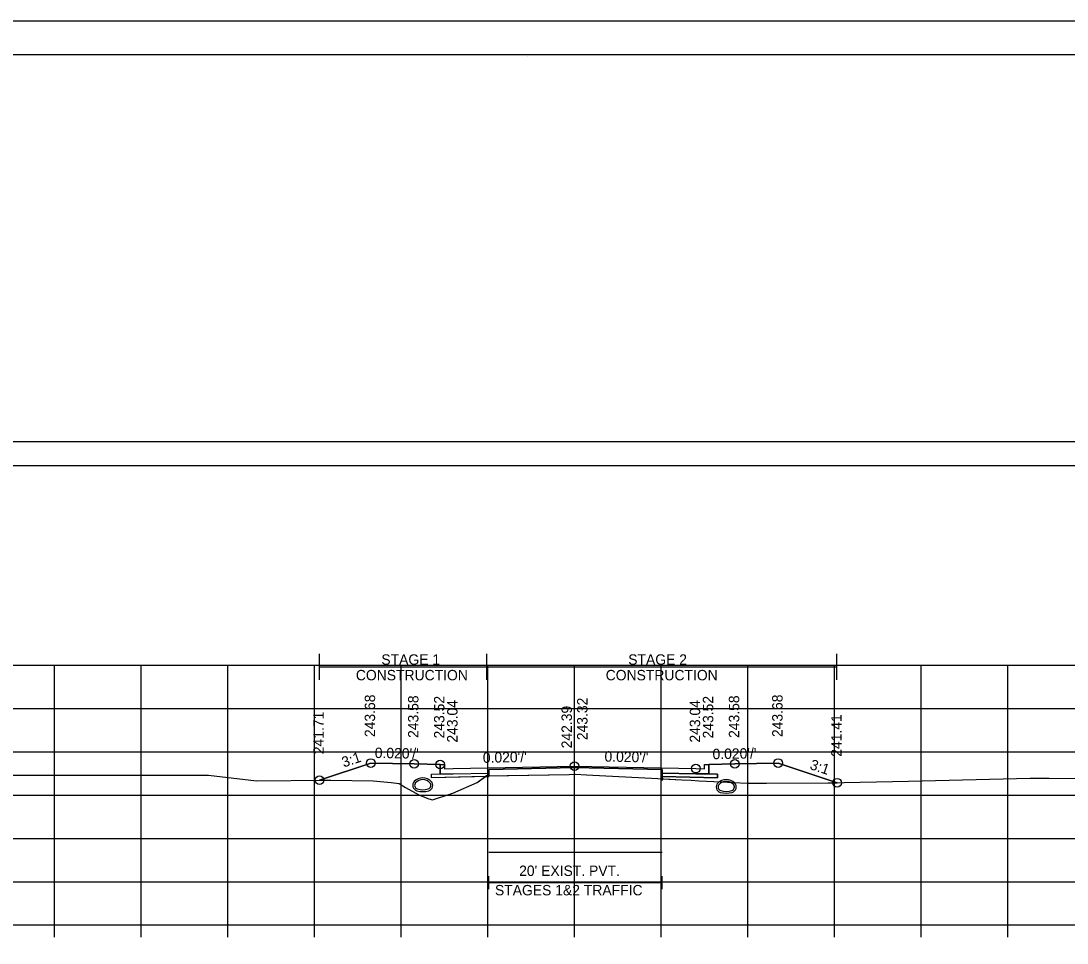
# Model space of a CAD drawing. Extents: x 1369627 to 1374022, y 380035 to 398173.
# Drawn here: x 1372034.6 to 1372155.4, y 383132.4 to 383238.8 of the extents above; entities that cross this region are included whole.
import ezdxf

# ---------------------------------------------------------------- set-up
doc = ezdxf.new("R2010")
doc.units = 0
for name, color, linetype in [('Default', 7, 'Continuous'), ('R_Alt Surface', 7, 'Continuous'), ('R_Axis', 7, 'Continuous'), ('R_Axis Annot', 7, 'Continuous'), ('R_Border', 7, 'Continuous'), ('R_Exist Surface', 7, 'Continuous'), ('R_Fin Surface', 7, 'Continuous'), ('R_Grid', 7, 'Continuous'), ('R_MOT', 7, 'Continuous'), ('R_No Plot', 7, 'Continuous'), ('R_Water', 7, 'Continuous'), ('R_Xsect Elev', 7, 'Continuous'), ('R_Xsect Slope', 7, 'Continuous'), ('T_Vehicle Path Rt', 7, 'Continuous')]:
    doc.layers.add(name, color=color, linetype=linetype)

msp = doc.modelspace()

# ---------------------------------------------------------------- linework, layer by layer
at = {"layer": 'Default'}
for p, q in [((1372088.64, 383138.64), (1372088.64, 383140.14)), ((1372088.64, 383139.39), (1372108.64, 383139.39)), ((1372108.64, 383138.64), (1372108.64, 383140.14))]:
    msp.add_line(p, q, dxfattribs=at)
msp.add_lwpolyline([(1371948.53, 383187.54), (1372248.53, 383187.54), (1372248.53, 383190.24), (1371948.53, 383190.24)], close=True, dxfattribs=at)
at = {"layer": 'R_Alt Surface'}
msp.add_lwpolyline([(1372083.03, 383153.02), (1372083.03, 383151.92), (1372084.53, 383151.95), (1372088.64, 383152.03), (1372088.64, 383152.45), (1372098.53, 383152.65), (1372108.64, 383152.44), (1372108.64, 383152.03), (1372112.53, 383151.95), (1372114.03, 383151.92), (1372114.03, 383153.02)], dxfattribs=at)
for points in [[(1372082.03, 383151.9), (1372083.03, 383151.92), (1372084.53, 383151.95), (1372088.64, 383152.03), (1372088.64, 383151.61), (1372082.03, 383151.48)], [(1372115.03, 383151.9), (1372114.03, 383151.92), (1372112.53, 383151.95), (1372108.64, 383152.03), (1372108.64, 383151.61), (1372115.03, 383151.48)]]:
    msp.add_lwpolyline(points, close=True, dxfattribs=at)
at = {"layer": 'R_Axis'}
for p, q in [((1371948.53, 383134.49), (1372248.53, 383134.49)), ((1372038.53, 383133.09), (1372038.53, 383134.49)), ((1372048.53, 383133.09), (1372048.53, 383134.49)), ((1372058.53, 383133.09), (1372058.53, 383134.49)), ((1372068.53, 383133.09), (1372068.53, 383134.49)), ((1372078.53, 383133.09), (1372078.53, 383134.49)), ((1372088.53, 383133.09), (1372088.53, 383134.49)), ((1372098.53, 383133.09), (1372098.53, 383134.49)), ((1372108.53, 383133.09), (1372108.53, 383134.49)), ((1372118.53, 383133.09), (1372118.53, 383134.49)), ((1372128.53, 383133.09), (1372128.53, 383134.49)), ((1372138.53, 383133.09), (1372138.53, 383134.49)), ((1372148.53, 383133.09), (1372148.53, 383134.49))]:
    msp.add_line(p, q, dxfattribs=at)
at = {"layer": 'R_Border'}
for p, q in [((1371940.53, 383234.95), (1372256.71, 383234.95)), ((1372093.05, 383234.69), (1372093.05, 383234.69)), ((1372093.05, 383234.69), (1372093.05, 383234.69))]:
    msp.add_line(p, q, dxfattribs=at)
at = {"layer": 'R_Exist Surface'}
msp.add_lwpolyline([(1372015.27, 383151.77), (1372044.13, 383151.79), (1372055.21, 383151.8), (1372056.3, 383151.77), (1372061.83, 383151.14), (1372069.81, 383151.21), (1372070.09, 383151.19), (1372070.42, 383151.19), (1372075.29, 383151.13), (1372077.37, 383150.93), (1372078.3, 383150.83), (1372079.04, 383150.37), (1372080.64, 383149.46), (1372081.71, 383149.05), (1372082.14, 383148.92), (1372084.24, 383149.61), (1372084.35, 383149.65), (1372084.5, 383149.72), (1372087.28, 383150.95), (1372088.26, 383151.63), (1372088.37, 383151.72), (1372097.93, 383151.87), (1372098.64, 383151.88), (1372099.9, 383151.82), (1372108.16, 383151.4), (1372110.92, 383151.24), (1372111.98, 383151.19), (1372112.89, 383151.14), (1372115.49, 383151.01), (1372116.88, 383150.94), (1372118.46, 383150.85), (1372120.7, 383150.86), (1372127.81, 383150.88), (1372137.06, 383151.09), (1372151.12, 383151.43), (1372153.3, 383151.43), (1372172.84, 383151.22)], dxfattribs=at)
at = {"layer": 'R_Fin Surface'}
msp.add_lwpolyline([(1372069.1, 383151.2), (1372075.02, 383153.18), (1372080.02, 383153.08), (1372083.02, 383153.02), (1372083.52, 383153.02), (1372083.53, 383152.52), (1372084.53, 383152.54), (1372086.53, 383152.58), (1372098.53, 383152.82), (1372110.53, 383152.58), (1372112.53, 383152.54), (1372113.53, 383152.52), (1372113.54, 383153.02), (1372114.04, 383153.02), (1372117.04, 383153.08), (1372122.04, 383153.18), (1372128.85, 383150.91)], dxfattribs=at)
at = {"layer": 'R_Grid'}
for p, q in [((1371948.53, 383164.49), (1372248.53, 383164.49)), ((1372038.53, 383134.49), (1372038.53, 383164.49)), ((1372048.53, 383134.49), (1372048.53, 383164.49)), ((1372058.53, 383134.49), (1372058.53, 383164.49)), ((1372068.53, 383134.49), (1372068.53, 383164.49)), ((1372078.53, 383134.49), (1372078.53, 383164.49)), ((1372088.53, 383134.49), (1372088.53, 383164.49)), ((1372098.53, 383134.49), (1372098.53, 383164.49)), ((1372108.53, 383134.49), (1372108.53, 383164.49)), ((1372118.53, 383134.49), (1372118.53, 383164.49)), ((1372128.53, 383134.49), (1372128.53, 383164.49)), ((1372138.53, 383134.49), (1372138.53, 383164.49)), ((1372148.53, 383134.49), (1372148.53, 383164.49)), ((1371948.53, 383159.49), (1372248.53, 383159.49)), ((1371948.53, 383154.49), (1372248.53, 383154.49)), ((1371948.53, 383149.49), (1372248.53, 383149.49)), ((1371948.53, 383144.49), (1372248.53, 383144.49)), ((1371948.53, 383139.49), (1372248.53, 383139.49)), ((1371948.53, 383134.49), (1372248.53, 383134.49))]:
    msp.add_line(p, q, dxfattribs=at)
at = {"layer": 'R_MOT'}
for p, q in [((1372069.1, 383162.77), (1372069.1, 383165.77)), ((1372088.4, 383162.77), (1372088.4, 383165.77)), ((1372128.79, 383162.77), (1372128.79, 383165.77)), ((1372069.1, 383164.27), (1372128.79, 383164.27))]:
    msp.add_line(p, q, dxfattribs=at)
at = {"layer": 'R_No Plot'}
msp.add_line((1371928.13, 383238.84), (1372261.46, 383238.84), dxfattribs=at)
for points in [[(1371928.12, 383238.84), (1372261.46, 383238.84), (1372261.46, 383025.5), (1371928.12, 383025.5)], [(1372174.45, 383234.95), (1372194.07, 383234.95), (1372194.07, 383225.07), (1372210.18, 383225.07), (1372233.38, 383225.07), (1372233.38, 383192.4), (1372256.59, 383192.4), (1372256.71, 383029.49), (1371940.53, 383029.49), (1371940.53, 383234.95)]]:
    msp.add_lwpolyline(points, close=True, dxfattribs=at)
msp.add_lwpolyline([(1372088.64, 383142.88), (1372108.64, 383142.88)], dxfattribs=at)
for centre in [(1372075.02, 383153.18), (1372080.02, 383153.08), (1372083.02, 383153.02), (1372098.53, 383152.82), (1372112.53, 383152.54), (1372117.04, 383153.08), (1372122.04, 383153.18), (1372069.1, 383151.2), (1372128.85, 383150.91)]:
    msp.add_circle(centre, 0.5, dxfattribs=at)
at = {"layer": 'R_Water'}
for centre, radius, start, end in [((1372081.02, 383150.12), 1.35, 43.6485, 136.3515), ((1372080.51, 383150.61), 0.646, 136.3515, 253.9529), ((1372080.51, 383150.61), 0.438, 136.3515, 253.9529), ((1372081.02, 383150.12), 1.15, 43.6485, 136.3515), ((1372081.02, 383152.39), 2.29, 253.9529, 286.0471), ((1372081.53, 383150.61), 0.438, 286.0471, 43.6485), ((1372081.53, 383150.61), 0.646, 286.0471, 43.6485), ((1372115.53, 383150.42), 0.646, 136.3515, 253.9529), ((1372116.04, 383149.93), 1.35, 43.6485, 136.3515), ((1372115.53, 383150.42), 0.438, 136.3515, 253.9529), ((1372116.04, 383149.93), 1.15, 43.6485, 136.3515), ((1372116.55, 383150.42), 0.438, 286.0471, 43.6485), ((1372116.55, 383150.42), 0.646, 286.0471, 43.6485), ((1372081.02, 383152.39), 2.5, 253.9529, 286.0471), ((1372116.04, 383152.2), 2.5, 253.9529, 286.0471), ((1372116.04, 383152.2), 2.29, 253.9529, 286.0471)]:
    msp.add_arc(centre, radius, start, end, dxfattribs=at)
at = {"layer": 'R_Xsect Elev'}
msp.add_line((1372098.53, 383151.88), (1372098.53, 383161.88), dxfattribs=at)
at = {"layer": 'T_Vehicle Path Rt'}
for p, q in [((1372083.03, 383151.92), (1372083.03, 383153.02)), ((1372114.04, 383153.02), (1372114.03, 383151.92)), ((1372088.23, 383151.61), (1372082.03, 383151.48)), ((1372088.23, 383151.61), (1372088.64, 383151.61)), ((1372088.64, 383152.03), (1372088.64, 383151.72)), ((1372088.64, 383151.61), (1372088.64, 383151.72)), ((1372108.64, 383151.61), (1372108.64, 383152.03)), ((1372108.64, 383151.61), (1372108.64, 383151.16)), ((1372108.64, 383151.37), (1372108.64, 383151.61)), ((1372108.64, 383151.61), (1372108.64, 383151.37)), ((1372108.64, 383151.37), (1372110.92, 383151.24))]:
    msp.add_line(p, q, dxfattribs=at)
for points in [[(1372083.03, 383153.02), (1372083.02, 383153.02), (1372080.02, 383153.08), (1372075.02, 383153.18), (1372069.1, 383151.2)], [(1372108.64, 383152.03), (1372108.64, 383152.44), (1372098.53, 383152.65), (1372088.64, 383152.45), (1372088.64, 383152.03)], [(1372128.85, 383150.91), (1372122.04, 383153.18), (1372117.04, 383153.08), (1372114.04, 383153.02)], [(1372069.1, 383151.2), (1372069.81, 383151.21), (1372070.09, 383151.19), (1372070.42, 383151.19), (1372075.29, 383151.13), (1372077.37, 383150.93), (1372078.3, 383150.83), (1372079.04, 383150.37), (1372080.64, 383149.46), (1372081.71, 383149.05), (1372082.14, 383148.92), (1372084.24, 383149.61), (1372084.35, 383149.65), (1372084.5, 383149.72), (1372087.28, 383150.95), (1372088.23, 383151.61)], [(1372082.03, 383151.48), (1372082.03, 383151.9), (1372083.03, 383151.92)], [(1372088.64, 383151.72), (1372088.37, 383151.72), (1372088.26, 383151.63), (1372088.23, 383151.61)], [(1372088.64, 383151.72), (1372097.93, 383151.87), (1372098.64, 383151.88), (1372099.9, 383151.82), (1372108.16, 383151.4), (1372108.64, 383151.37)], [(1372114.03, 383151.92), (1372115.03, 383151.9), (1372115.03, 383151.48), (1372108.64, 383151.61)], [(1372110.92, 383151.24), (1372111.98, 383151.19), (1372112.89, 383151.14), (1372115.49, 383151.01), (1372116.88, 383150.94), (1372118.46, 383150.85), (1372120.7, 383150.86), (1372127.81, 383150.88), (1372128.85, 383150.91)]]:
    msp.add_lwpolyline(points, dxfattribs=at)

# ---------------------------------------------------------------- texts
at = {"layer": 'R_Axis Annot'}
for s, p in [("20' EXIST. PVT.", (1372092.14, 383140.15)), ('STAGES 1&2 TRAFFIC', (1372089.35, 383137.91))]:
    msp.add_text(s, height=1.2, dxfattribs=at).set_placement(p)
at = {"layer": 'R_MOT'}
for s, p in [('STAGE 1', (1372076.24, 383164.53)), ('STAGE 2', (1372104.73, 383164.53)), ('CONSTRUCTION', (1372073.3, 383162.73)), ('CONSTRUCTION', (1372102.13, 383162.73))]:
    msp.add_text(s, height=1.2, dxfattribs=at).set_placement(p)
at = {"layer": 'R_Xsect Elev'}
for s, p in [('243.68', (1372075.52, 383156.18)), ('243.68', (1372122.54, 383156.18)), ('243.58', (1372080.52, 383156.08)), ('243.52', (1372083.52, 383156.02)), ('243.04', (1372085.03, 383155.54)), ('243.32', (1372100.03, 383155.82)), ('243.04', (1372113.03, 383155.54)), ('243.52', (1372114.54, 383156.02)), ('243.58', (1372117.54, 383156.08)), ('241.71', (1372069.6, 383154.2)), ('242.39', (1372098.23, 383154.88)), ('241.41', (1372129.35, 383153.91))]:
    msp.add_text(s, height=1.2, rotation=90, dxfattribs=at).set_placement(p)
at = {"layer": 'R_Xsect Slope'}
for s, rotation, p in [("0.020'/'", 358.8542, (1372075.47, 383153.77)), ("0.020'/'", 1.1458, (1372114.47, 383153.62)), ('3:1', 18.4332, (1372071.9, 383152.66)), ("0.020'/'", 1.1458, (1372087.96, 383153.2)), ("0.020'/'", 358.8542, (1372101.98, 383153.35)), ('3:1', 341.5668, (1372125.6, 383152.51))]:
    msp.add_text(s, height=1.2, rotation=rotation, dxfattribs=at).set_placement(p)

doc.saveas('drawing.dxf')
